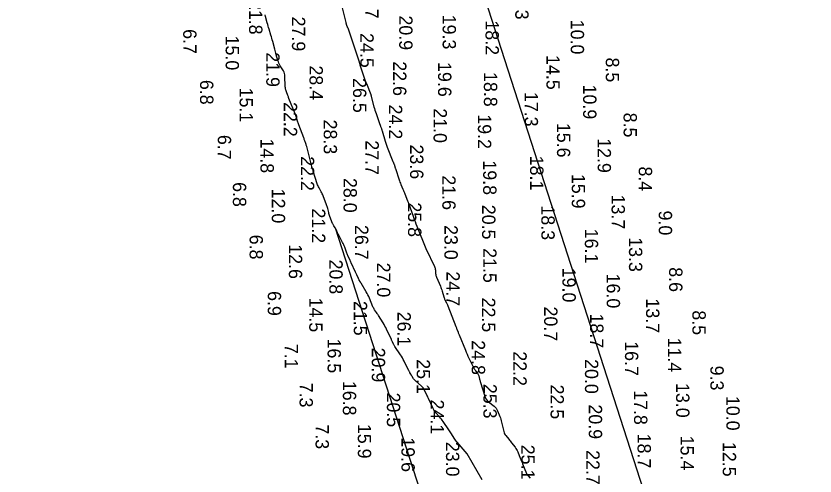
# Model space of a CAD drawing. Extents: x 1178573 to 1187098, y 693282 to 751751.
# Drawn here: x 1183256 to 1184005, y 738845 to 739276 of the extents above; entities that cross this region are included whole.
import ezdxf

# ---------------------------------------------------------------- set-up
doc = ezdxf.new("R2010")
doc.units = 0
for name, color, linetype in [('G-ANNO-PATT', 7, 'Continuous'), ('V-HYDS-MAJR', 7, 'Continuous'), ('V-HYDS-SOUN', 7, 'Continuous'), ('V-HYDS-SOUN-EXSS', 7, 'Continuous')]:
    doc.layers.add(name, color=color, linetype=linetype)

msp = doc.modelspace()

# ---------------------------------------------------------------- linework, layer by layer
at = {"layer": 'G-ANNO-PATT'}
for points in [[(1183884.78, 738706.45), (1183565.77, 739696.46), (1183463.01, 741660.48), (1183454.74, 741818.49), (1183255.55, 742478.87)], [(1183559.04, 739294.25), (1183565.08, 739270.1), (1183565.18, 739269.73), (1183565.28, 739269.36), (1183565.39, 739268.98), (1183565.5, 739268.62), (1183566.07, 739266.86), (1183566.14, 739266.63), (1183566.23, 739266.41), (1183566.33, 739266.2), (1183566.44, 739265.99), (1183566.9, 739265.15), (1183567.01, 739264.94), (1183567.1, 739264.73), (1183567.19, 739264.51), (1183567.27, 739264.28), (1183577.28, 739234.2), (1183577.32, 739234.06), (1183577.37, 739233.92), (1183577.41, 739233.79), (1183577.45, 739233.65), (1183577.62, 739233.09), (1183577.66, 739232.95), (1183577.7, 739232.82), (1183577.74, 739232.68), (1183577.77, 739232.54), (1183578.02, 739231.53), (1183578.07, 739231.31), (1183578.13, 739231.1), (1183578.19, 739230.89), (1183578.26, 739230.67), (1183581.77, 739220.11), (1183582.37, 739218.33), (1183583, 739216.55), (1183583.66, 739214.78), (1183584.34, 739213.02), (1183588.41, 739202.66), (1183588.45, 739202.57), (1183588.48, 739202.49), (1183588.51, 739202.4), (1183588.54, 739202.31), (1183588.67, 739201.96), (1183588.7, 739201.88), (1183588.73, 739201.79), (1183588.75, 739201.7), (1183588.77, 739201.62), (1183588.85, 739201.27), (1183588.87, 739201.18), (1183588.89, 739201.09), (1183588.91, 739201.01), (1183588.93, 739200.92), (1183591.44, 739191.25), (1183591.89, 739189.61), (1183592.36, 739187.99), (1183592.88, 739186.38), (1183593.43, 739184.77), (1183597.02, 739174.63), (1183597.19, 739174.14), (1183597.36, 739173.64), (1183597.54, 739173.15), (1183597.71, 739172.66), (1183598.41, 739170.69), (1183598.58, 739170.2), (1183598.75, 739169.7), (1183598.91, 739169.21), (1183599.06, 739168.71), (1183602.14, 739158.8), (1183602.72, 739156.99), (1183603.33, 739155.18), (1183603.96, 739153.39), (1183604.61, 739151.6), (1183608.46, 739141.4), (1183608.6, 739141.04), (1183608.75, 739140.68), (1183608.92, 739140.33), (1183609.09, 739139.98), (1183609.79, 739138.58), (1183609.96, 739138.23), (1183610.11, 739137.87), (1183610.25, 739137.51), (1183610.37, 739137.13), (1183610.97, 739135.06), (1183611.11, 739134.6), (1183611.26, 739134.13), (1183611.4, 739133.66), (1183611.56, 739133.19), (1183615.04, 739122.67), (1183615.43, 739121.54), (1183615.85, 739120.41), (1183616.29, 739119.3), (1183616.76, 739118.2), (1183618.69, 739113.81), (1183619.16, 739112.71), (1183619.62, 739111.61), (1183620.07, 739110.5), (1183620.5, 739109.38), (1183622.93, 739103), (1183623.47, 739101.56), (1183624.01, 739100.12), (1183624.54, 739098.68), (1183625.07, 739097.24), (1183628.57, 739087.55), (1183629.33, 739085.46), (1183630.11, 739083.37), (1183630.91, 739081.29), (1183631.72, 739079.21), (1183640.08, 739058.03), (1183640.1, 739057.98), (1183640.12, 739057.93), (1183640.14, 739057.89), (1183640.17, 739057.84), (1183640.28, 739057.66), (1183640.3, 739057.62), (1183640.33, 739057.57), (1183640.35, 739057.53), (1183640.38, 739057.48), (1183648.29, 739041.12), (1183648.62, 739040.35), (1183648.87, 739039.56), (1183649.04, 739038.75), (1183649.14, 739037.92), (1183649.37, 739034.57), (1183649.46, 739033.73), (1183649.62, 739032.92), (1183649.85, 739032.12), (1183650.14, 739031.34), (1183653.8, 739022.67), (1183654.26, 739021.56), (1183654.68, 739020.43), (1183655.07, 739019.29), (1183655.42, 739018.14), (1183657.05, 739012.65), (1183657.28, 739011.93), (1183657.53, 739011.23), (1183657.82, 739010.53), (1183658.14, 739009.85), (1183659.49, 739007.16), (1183659.82, 739006.48), (1183660.13, 739005.8), (1183660.42, 739005.1), (1183660.71, 739004.41), (1183668.29, 738984.92), (1183668.55, 738984.25), (1183668.81, 738983.59), (1183669.07, 738982.92), (1183669.33, 738982.26), (1183670.37, 738979.59), (1183670.64, 738978.93), (1183670.9, 738978.26), (1183671.17, 738977.6), (1183671.44, 738976.94), (1183677.28, 738962.62), (1183678.06, 738960.77), (1183678.87, 738958.94), (1183679.71, 738957.13), (1183680.59, 738955.33), (1183685.3, 738945.9), (1183685.64, 738945.26), (1183686.01, 738944.62), (1183686.41, 738944.01), (1183686.85, 738943.41), (1183688.63, 738941.07), (1183689.04, 738940.47), (1183689.38, 738939.83), (1183689.66, 738939.16), (1183689.88, 738938.47), (1183690.64, 738935.4), (1183690.84, 738934.66), (1183691.04, 738933.91), (1183691.25, 738933.17), (1183691.46, 738932.43), (1183695.4, 738919.36), (1183695.96, 738917.89), (1183696.73, 738916.55), (1183697.69, 738915.36), (1183698.86, 738914.3), (1183704.25, 738910.08), (1183705.29, 738909.16), (1183706.18, 738908.13), (1183706.93, 738906.98), (1183707.53, 738905.73), (1183709.63, 738900.5), (1183710.13, 738899.18), (1183710.57, 738897.85), (1183710.97, 738896.5), (1183711.3, 738895.13), (1183713.32, 738886.22), (1183713.62, 738885.2), (1183714.02, 738884.23), (1183714.54, 738883.32), (1183715.17, 738882.46), (1183717.92, 738879.13), (1183718.61, 738878.3), (1183719.29, 738877.46), (1183719.96, 738876.62), (1183720.63, 738875.78), (1183723.99, 738871.54), (1183724.73, 738870.53), (1183725.39, 738869.47), (1183725.97, 738868.36), (1183726.48, 738867.21), (1183728.79, 738861.34), (1183729.33, 738859.98), (1183729.88, 738858.61), (1183730.43, 738857.24), (1183730.98, 738855.88), (1183734.56, 738847.06), (1183734.85, 738846.42), (1183735.2, 738845.81), (1183735.6, 738845.24), (1183736.06, 738844.7), (1183737.98, 738842.61)], [(1183693.04, 738841.12), (1183679.02, 738865.37), (1183669.45, 738876.28), (1183668.7, 738877.18), (1183667.99, 738878.1), (1183667.32, 738879.05), (1183666.7, 738880.03), (1183664.26, 738884.02), (1183663.64, 738885.01), (1183663.02, 738885.99), (1183662.38, 738886.97), (1183661.72, 738887.94), (1183656.35, 738895.8), (1183655.58, 738896.89), (1183654.78, 738897.95), (1183653.94, 738898.99), (1183653.07, 738900), (1183649.54, 738903.99), (1183648.7, 738905.01), (1183647.94, 738906.09), (1183647.26, 738907.22), (1183646.66, 738908.41), (1183642.54, 738917.47), (1183642.08, 738918.47), (1183641.62, 738919.45), (1183641.15, 738920.44), (1183640.67, 738921.42), (1183638.73, 738925.34), (1183638.21, 738926.29), (1183637.6, 738927.18), (1183636.91, 738928.01), (1183636.14, 738928.77), (1183630.19, 738934.15), (1183629.77, 738934.56), (1183629.38, 738934.99), (1183629.02, 738935.45), (1183628.69, 738935.93), (1183627.36, 738938.02), (1183627.08, 738938.45), (1183626.81, 738938.89), (1183626.55, 738939.33), (1183626.29, 738939.77), (1183625.26, 738941.55), (1183625, 738942), (1183624.76, 738942.45), (1183624.52, 738942.91), (1183624.28, 738943.37), (1183619.84, 738952.3), (1183619.02, 738953.87), (1183618.16, 738955.41), (1183617.25, 738956.92), (1183616.29, 738958.4), (1183611.06, 738966.21), (1183610.73, 738966.71), (1183610.43, 738967.23), (1183610.14, 738967.76), (1183609.87, 738968.29), (1183608.85, 738970.47), (1183608.59, 738971.01), (1183608.34, 738971.55), (1183608.08, 738972.1), (1183607.83, 738972.64), (1183603.31, 738982.43), (1183602.59, 738983.91), (1183601.83, 738985.37), (1183601.03, 738986.8), (1183600.17, 738988.21), (1183595.8, 738995.18), (1183595.35, 738995.87), (1183594.91, 738996.56), (1183594.45, 738997.24), (1183593.99, 738997.92), (1183592.12, 739000.63), (1183591.67, 739001.32), (1183591.25, 739002.03), (1183590.88, 739002.76), (1183590.54, 739003.51), (1183587.22, 739011.4), (1183586.53, 739012.96), (1183585.8, 739014.49), (1183585, 739015.99), (1183584.16, 739017.46), (1183579.38, 739025.5), (1183579.17, 739025.87), (1183578.95, 739026.24), (1183578.74, 739026.61), (1183578.53, 739026.99), (1183577.71, 739028.48), (1183577.5, 739028.86), (1183577.31, 739029.24), (1183577.11, 739029.62), (1183576.93, 739030), (1183575.38, 739033.27), (1183575.06, 739033.95), (1183574.74, 739034.62), (1183574.43, 739035.3), (1183574.12, 739035.98), (1183570.19, 739044.56), (1183569.84, 739045.33), (1183569.48, 739046.1), (1183569.13, 739046.88), (1183568.77, 739047.65), (1183567.35, 739050.74), (1183567, 739051.52), (1183566.67, 739052.3), (1183566.35, 739053.09), (1183566.04, 739053.89), (1183564.03, 739059.31), (1183563.58, 739060.47), (1183563.09, 739061.61), (1183562.56, 739062.73), (1183561.98, 739063.84), (1183558.37, 739070.55), (1183558.07, 739071.13), (1183557.79, 739071.71), (1183557.52, 739072.29), (1183557.27, 739072.89), (1183556.26, 739075.35), (1183556.02, 739075.91), (1183555.75, 739076.45), (1183555.46, 739076.98), (1183555.14, 739077.5), (1183555.03, 739077.67)], [(1183555.03, 739077.67), (1183691.64, 738653.74), (1183705.44, 738610.92), (1184201.87, 737980.6)]]:
    msp.add_lwpolyline(points, dxfattribs=at)
at = {"layer": 'V-HYDS-MAJR'}
for points in [[(1183559.04, 739294.25), (1183565.08, 739270.1), (1183565.18, 739269.73), (1183565.28, 739269.36), (1183565.39, 739268.98), (1183565.5, 739268.62), (1183566.07, 739266.86), (1183566.14, 739266.63), (1183566.23, 739266.41), (1183566.33, 739266.2), (1183566.44, 739265.99), (1183566.9, 739265.15), (1183567.01, 739264.94), (1183567.1, 739264.73), (1183567.19, 739264.51), (1183567.27, 739264.28), (1183577.28, 739234.2), (1183577.32, 739234.06), (1183577.37, 739233.92), (1183577.41, 739233.79), (1183577.45, 739233.65), (1183577.62, 739233.09), (1183577.66, 739232.95), (1183577.7, 739232.82), (1183577.74, 739232.68), (1183577.77, 739232.54), (1183578.02, 739231.53), (1183578.07, 739231.31), (1183578.13, 739231.1), (1183578.19, 739230.89), (1183578.26, 739230.67), (1183581.77, 739220.11), (1183582.37, 739218.33), (1183583, 739216.55), (1183583.66, 739214.78), (1183584.34, 739213.02), (1183588.41, 739202.66), (1183588.45, 739202.57), (1183588.48, 739202.49), (1183588.51, 739202.4), (1183588.54, 739202.31), (1183588.67, 739201.96), (1183588.7, 739201.88), (1183588.73, 739201.79), (1183588.75, 739201.7), (1183588.77, 739201.62), (1183588.85, 739201.27), (1183588.87, 739201.18), (1183588.89, 739201.09), (1183588.91, 739201.01), (1183588.93, 739200.92), (1183591.44, 739191.25), (1183591.89, 739189.61), (1183592.36, 739187.99), (1183592.88, 739186.38), (1183593.43, 739184.77), (1183597.02, 739174.63), (1183597.19, 739174.14), (1183597.36, 739173.64), (1183597.54, 739173.15), (1183597.71, 739172.66), (1183598.41, 739170.69), (1183598.58, 739170.2), (1183598.75, 739169.7), (1183598.91, 739169.21), (1183599.06, 739168.71), (1183602.14, 739158.8), (1183602.72, 739156.99), (1183603.33, 739155.18), (1183603.96, 739153.39), (1183604.61, 739151.6), (1183608.46, 739141.4), (1183608.6, 739141.04), (1183608.75, 739140.68), (1183608.92, 739140.33), (1183609.09, 739139.98), (1183609.79, 739138.58), (1183609.96, 739138.23), (1183610.11, 739137.87), (1183610.25, 739137.51), (1183610.37, 739137.13), (1183610.97, 739135.06), (1183611.11, 739134.6), (1183611.26, 739134.13), (1183611.4, 739133.66), (1183611.56, 739133.19), (1183615.04, 739122.67), (1183615.43, 739121.54), (1183615.85, 739120.41), (1183616.29, 739119.3), (1183616.76, 739118.2), (1183618.69, 739113.81), (1183619.16, 739112.71), (1183619.62, 739111.61), (1183620.07, 739110.5), (1183620.5, 739109.38), (1183622.93, 739103), (1183623.47, 739101.56), (1183624.01, 739100.12), (1183624.54, 739098.68), (1183625.07, 739097.24), (1183628.57, 739087.55), (1183629.33, 739085.46), (1183630.11, 739083.37), (1183630.91, 739081.29), (1183631.72, 739079.21), (1183640.08, 739058.03), (1183640.1, 739057.98), (1183640.12, 739057.93), (1183640.14, 739057.89), (1183640.17, 739057.84), (1183640.28, 739057.66), (1183640.3, 739057.62), (1183640.33, 739057.57), (1183640.35, 739057.53), (1183640.38, 739057.48), (1183648.29, 739041.12), (1183648.62, 739040.35), (1183648.87, 739039.56), (1183649.04, 739038.75), (1183649.14, 739037.92), (1183649.37, 739034.57), (1183649.46, 739033.73), (1183649.62, 739032.92), (1183649.85, 739032.12), (1183650.14, 739031.34), (1183653.8, 739022.67), (1183654.26, 739021.56), (1183654.68, 739020.43), (1183655.07, 739019.29), (1183655.42, 739018.14), (1183657.05, 739012.65), (1183657.28, 739011.93), (1183657.53, 739011.23), (1183657.82, 739010.53), (1183658.14, 739009.85), (1183659.49, 739007.16), (1183659.82, 739006.48), (1183660.13, 739005.8), (1183660.42, 739005.1), (1183660.71, 739004.41), (1183668.29, 738984.92), (1183668.55, 738984.25), (1183668.81, 738983.59), (1183669.07, 738982.92), (1183669.33, 738982.26), (1183670.37, 738979.59), (1183670.64, 738978.93), (1183670.9, 738978.26), (1183671.17, 738977.6), (1183671.44, 738976.94), (1183677.28, 738962.62), (1183678.06, 738960.77), (1183678.87, 738958.94), (1183679.71, 738957.13), (1183680.59, 738955.33), (1183685.3, 738945.9), (1183685.64, 738945.26), (1183686.01, 738944.62), (1183686.41, 738944.01), (1183686.85, 738943.41), (1183688.63, 738941.07), (1183689.04, 738940.47), (1183689.38, 738939.83), (1183689.66, 738939.16), (1183689.88, 738938.47), (1183690.64, 738935.4), (1183690.84, 738934.66), (1183691.04, 738933.91), (1183691.25, 738933.17), (1183691.46, 738932.43), (1183695.4, 738919.36), (1183695.96, 738917.89), (1183696.73, 738916.55), (1183697.69, 738915.36), (1183698.86, 738914.3), (1183704.25, 738910.08), (1183705.29, 738909.16), (1183706.18, 738908.13), (1183706.93, 738906.98), (1183707.53, 738905.73), (1183709.63, 738900.5), (1183710.13, 738899.18), (1183710.57, 738897.85), (1183710.97, 738896.5), (1183711.3, 738895.13), (1183713.32, 738886.22), (1183713.62, 738885.2), (1183714.02, 738884.23), (1183714.54, 738883.32), (1183715.17, 738882.46), (1183717.92, 738879.13), (1183718.61, 738878.3), (1183719.29, 738877.46), (1183719.96, 738876.62), (1183720.63, 738875.78), (1183723.99, 738871.54), (1183724.73, 738870.53), (1183725.39, 738869.47), (1183725.97, 738868.36), (1183726.48, 738867.21), (1183728.79, 738861.34), (1183729.33, 738859.98), (1183729.88, 738858.61), (1183730.43, 738857.24), (1183730.98, 738855.88), (1183734.56, 738847.06), (1183734.85, 738846.42), (1183735.2, 738845.81), (1183735.6, 738845.24), (1183736.06, 738844.7), (1183737.98, 738842.61)], [(1183693.04, 738841.12), (1183679.02, 738865.37), (1183669.45, 738876.28), (1183668.7, 738877.18), (1183667.99, 738878.1), (1183667.32, 738879.05), (1183666.7, 738880.03), (1183664.26, 738884.02), (1183663.64, 738885.01), (1183663.02, 738885.99), (1183662.38, 738886.97), (1183661.72, 738887.94), (1183656.35, 738895.8), (1183655.58, 738896.89), (1183654.78, 738897.95), (1183653.94, 738898.99), (1183653.07, 738900), (1183649.54, 738903.99), (1183648.7, 738905.01), (1183647.94, 738906.09), (1183647.26, 738907.22), (1183646.66, 738908.41), (1183642.54, 738917.47), (1183642.08, 738918.47), (1183641.62, 738919.45), (1183641.15, 738920.44), (1183640.67, 738921.42), (1183638.73, 738925.34), (1183638.21, 738926.29), (1183637.6, 738927.18), (1183636.91, 738928.01), (1183636.14, 738928.77), (1183630.19, 738934.15), (1183629.77, 738934.56), (1183629.38, 738934.99), (1183629.02, 738935.45), (1183628.69, 738935.93), (1183627.36, 738938.02), (1183627.08, 738938.45), (1183626.81, 738938.89), (1183626.55, 738939.33), (1183626.29, 738939.77), (1183625.26, 738941.55), (1183625, 738942), (1183624.76, 738942.45), (1183624.52, 738942.91), (1183624.28, 738943.37), (1183619.84, 738952.3), (1183619.02, 738953.87), (1183618.16, 738955.41), (1183617.25, 738956.92), (1183616.29, 738958.4), (1183611.06, 738966.21), (1183610.73, 738966.71), (1183610.43, 738967.23), (1183610.14, 738967.76), (1183609.87, 738968.29), (1183608.85, 738970.47), (1183608.59, 738971.01), (1183608.34, 738971.55), (1183608.08, 738972.1), (1183607.83, 738972.64), (1183603.31, 738982.43), (1183602.59, 738983.91), (1183601.83, 738985.37), (1183601.03, 738986.8), (1183600.17, 738988.21), (1183595.8, 738995.18), (1183595.35, 738995.87), (1183594.91, 738996.56), (1183594.45, 738997.24), (1183593.99, 738997.92), (1183592.12, 739000.63), (1183591.67, 739001.32), (1183591.25, 739002.03), (1183590.88, 739002.76), (1183590.54, 739003.51), (1183587.22, 739011.4), (1183586.53, 739012.96), (1183585.8, 739014.49), (1183585, 739015.99), (1183584.16, 739017.46), (1183579.38, 739025.5), (1183579.17, 739025.87), (1183578.95, 739026.24), (1183578.74, 739026.61), (1183578.53, 739026.99), (1183577.71, 739028.48), (1183577.5, 739028.86), (1183577.31, 739029.24), (1183577.11, 739029.62), (1183576.93, 739030), (1183575.38, 739033.27), (1183575.06, 739033.95), (1183574.74, 739034.62), (1183574.43, 739035.3), (1183574.12, 739035.98), (1183570.19, 739044.56), (1183569.84, 739045.33), (1183569.48, 739046.1), (1183569.13, 739046.88), (1183568.77, 739047.65), (1183567.35, 739050.74), (1183567, 739051.52), (1183566.67, 739052.3), (1183566.35, 739053.09), (1183566.04, 739053.89), (1183564.03, 739059.31), (1183563.58, 739060.47), (1183563.09, 739061.61), (1183562.56, 739062.73), (1183561.98, 739063.84), (1183558.37, 739070.55), (1183558.07, 739071.13), (1183557.79, 739071.71), (1183557.52, 739072.29), (1183557.27, 739072.89), (1183556.26, 739075.35), (1183556.02, 739075.91), (1183555.75, 739076.45), (1183555.46, 739076.98), (1183555.14, 739077.5), (1183553.83, 739079.54), (1183553.51, 739080.06), (1183553.22, 739080.59), (1183552.96, 739081.14), (1183552.72, 739081.7), (1183550.15, 739088.25), (1183549.81, 739089.14), (1183549.51, 739090.05), (1183549.24, 739090.96), (1183548.99, 739091.88), (1183548.08, 739095.58), (1183547.84, 739096.5), (1183547.57, 739097.41), (1183547.28, 739098.32), (1183546.96, 739099.21), (1183543.81, 739107.63), (1183543.42, 739108.6), (1183543, 739109.54), (1183542.54, 739110.47), (1183542.04, 739111.37), (1183539.95, 739114.97), (1183539.46, 739115.88), (1183539.02, 739116.81), (1183538.63, 739117.77), (1183538.3, 739118.75), (1183534.57, 739130.81), (1183534.49, 739131.07), (1183534.41, 739131.32), (1183534.33, 739131.58), (1183534.25, 739131.83), (1183533.93, 739132.85), (1183533.85, 739133.1), (1183533.77, 739133.36), (1183533.7, 739133.61), (1183533.63, 739133.87), (1183528.39, 739153.83), (1183528.2, 739154.52), (1183528, 739155.2), (1183527.78, 739155.88), (1183527.55, 739156.55), (1183526.6, 739159.23), (1183526.36, 739159.9), (1183526.12, 739160.57), (1183525.88, 739161.24), (1183525.63, 739161.91), (1183521.1, 739174.23), (1183520.79, 739175.1), (1183520.48, 739175.96), (1183520.18, 739176.83), (1183519.87, 739177.7), (1183518.68, 739181.18), (1183518.38, 739182.05), (1183518.07, 739182.91), (1183517.74, 739183.77), (1183517.41, 739184.63), (1183511.69, 739199.04), (1183511.42, 739199.73), (1183511.16, 739200.41), (1183510.9, 739201.1), (1183510.65, 739201.79), (1183509.44, 739205.14), (1183509.3, 739205.54), (1183509.17, 739205.95), (1183509.05, 739206.36), (1183508.94, 739206.77), (1183508.52, 739208.42), (1183508.42, 739208.84), (1183508.35, 739209.26), (1183508.3, 739209.68), (1183508.28, 739210.11), (1183507.99, 739219.79), (1183507.86, 739221.15), (1183507.57, 739222.45), (1183507.1, 739223.71), (1183506.46, 739224.91), (1183503.57, 739229.63), (1183502.89, 739230.83), (1183502.29, 739232.07), (1183501.78, 739233.34), (1183501.35, 739234.65), (1183499.8, 739240), (1183499.41, 739241.34), (1183499.04, 739242.68), (1183498.67, 739244.02), (1183498.32, 739245.36), (1183496.45, 739252.5), (1183496.06, 739253.96), (1183495.65, 739255.41), (1183495.23, 739256.86), (1183494.79, 739258.3), (1183493.01, 739264.07), (1183492.57, 739265.51), (1183492.15, 739266.96), (1183491.74, 739268.41), (1183491.35, 739269.87), (1183489.78, 739275.88), (1183489.37, 739277.36)]]:
    msp.add_lwpolyline(points, dxfattribs=at)

# ---------------------------------------------------------------- texts
at = {"layer": 'V-HYDS-SOUN'}
for s, p in [('22.7 ', (1183583.26, 739306.44)), ('15.3 ', (1183724.1, 739305.52)), ('21.8 ', (1183474.28, 739291.45)), ('27.9 ', (1183514.53, 739275.8)), ('20.9 ', (1183615.19, 739276.88)), ('19.3 ', (1183655.93, 739277.57)), ('18.2 ', (1183696.17, 739272.22)), ('10.0 ', (1183776.14, 739272.85)), ('6.7', (1183412.47, 739264.03)), ('24.5 ', (1183578.71, 739260.32)), ('15.0 ', (1183452.29, 739257.96)), ('21.9 ', (1183490.42, 739242.3)), ('14.5 ', (1183753.38, 739239.69)), ('28.4 ', (1183531.03, 739229.94)), ('22.6 ', (1183609.41, 739233.83)), ('19.6 ', (1183651.63, 739233.11)), ('18.8 ', (1183694.65, 739223.73)), ('6.8', (1183428.28, 739216.37)), ('26.5 ', (1183571.85, 739218.07)), ('15.1 ', (1183465.39, 739209.12)), ('22.2 ', (1183506.9, 739195.58)), ('24.2 ', (1183605.52, 739193.21)), ('8.5', (1183825.75, 739185.63)), ('28.3 ', (1183544.31, 739179.14)), ('15.6 ', (1183763.24, 739176.06)), ('6.7', (1183444.95, 739164.75)), ('14.8 ', (1183485.01, 739161.39)), ('12.9 ', (1183801.41, 739161.66)), ('19.8 ', (1183693.96, 739140.82)), ('18.1 ', (1183738.03, 739145.21)), ('8.4', (1183839.99, 739135.12)), ('28.0 ', (1183562.95, 739124.3)), ('21.6 ', (1183655.63, 739126.78)), ('15.9 ', (1183777.13, 739128.16)), ('25.8 ', (1183623.46, 739101.42)), ('13.7 ', (1183814.46, 739108.74)), ('21.2 ', (1183533.35, 739095.71)), ('20.5 ', (1183692.98, 739099.14)), ('18.3 ', (1183748.58, 739098.53)), ('9.0', (1183858.73, 739093.72)), ('26.7 ', (1183573.71, 739080.16)), ('23.0 ', (1183657.6, 739080.1)), ('6.8', (1183474.8, 739071.06)), ('16.1 ', (1183789.37, 739076.68)), ('13.3 ', (1183830.8, 739068.74)), ('12.6 ', (1183511.6, 739062.08)), ('21.5 ', (1183694.03, 739058.45)), ('20.8 ', (1183549.64, 739047.75)), ('27.0 ', (1183594.35, 739044.87)), ('24.7 ', (1183659.47, 739036.59)), ('19.0 ', (1183768.36, 739040.08)), ('16.0 ', (1183809.9, 739034.53)), ('8.6', (1183868.47, 739040.53)), ('6.9', (1183491.86, 739018.14)), ('14.5 ', (1183530.74, 739012.06)), ('22.5 ', (1183692.85, 739012.03)), ('21.5 ', (1183572.57, 739008.88)), ('20.7 ', (1183751.17, 739003.65)), ('13.7 ', (1183846.84, 739011.23)), ('26.1 ', (1183613.55, 738998.82)), ('18.7 ', (1183794.35, 738997.09)), ('8.5', (1183890.32, 739000.07)), ('11.4 ', (1183867.41, 738974.43)), ('7.1', (1183507.74, 738968.59)), ('16.5 ', (1183547.97, 738973.58)), ('24.8 ', (1183683.23, 738971.99)), ('16.7 ', (1183827.06, 738971.11)), ('20.9 ', (1183589.44, 738965.04)), ('22.2 ', (1183722.29, 738961.62)), ('25.1 ', (1183631.63, 738954.2)), ('20.0 ', (1183789.49, 738954.28)), ('9.3', (1183907.18, 738948.15)), ('7.3', (1183521.65, 738932.17)), ('16.8 ', (1183562.3, 738933.9)), ('25.3 ', (1183694.22, 738931.08)), ('22.5 ', (1183757.22, 738930.4)), ('13.0 ', (1183875.02, 738931.84)), ('20.5 ', (1183603.61, 738922.89)), ('17.8 ', (1183835.53, 738925.14)), ('24.1 ', (1183644.69, 738916.31)), ('10.0 ', (1183922.17, 738919.74)), ('20.9 ', (1183793.08, 738911.75)), ('7.3', (1183536.68, 738893.03)), ('15.9 ', (1183576.35, 738893.51)), ('18.7 ', (1183838.87, 738884.3)), ('19.6 ', (1183617.25, 738880.85)), ('23.0 ', (1183659.08, 738876.66)), ('15.4 ', (1183879.19, 738882.4)), ('12.5 ', (1183918.8, 738876.53)), ('25.1 ', (1183729.76, 738873.92)), ('22.7 ', (1183790.74, 738868.88))]:
    msp.add_text(s, height=12.5, rotation=270, dxfattribs=at).set_placement(p)
at = {"layer": 'V-HYDS-SOUN-EXSS'}
for s, p in [('8.5', (1183809.05, 739237.37)), ('10.9 ', (1183787.76, 739211.98)), ('17.3 ', (1183732.93, 739205.09)), ('21.0 ', (1183647.4, 739189.72)), ('19.2 ', (1183689.02, 739184.1)), ('27.7 ', (1183583.52, 739159.65)), ('23.6 ', (1183625.38, 739155.72)), ('22.2 ', (1183522.91, 739144.79)), ('6.8', (1183459.12, 739120.43)), ('12.0 ', (1183495.59, 739114.29))]:
    msp.add_text(s, height=12.5, rotation=270, dxfattribs=at).set_placement(p)

doc.saveas('drawing.dxf')
